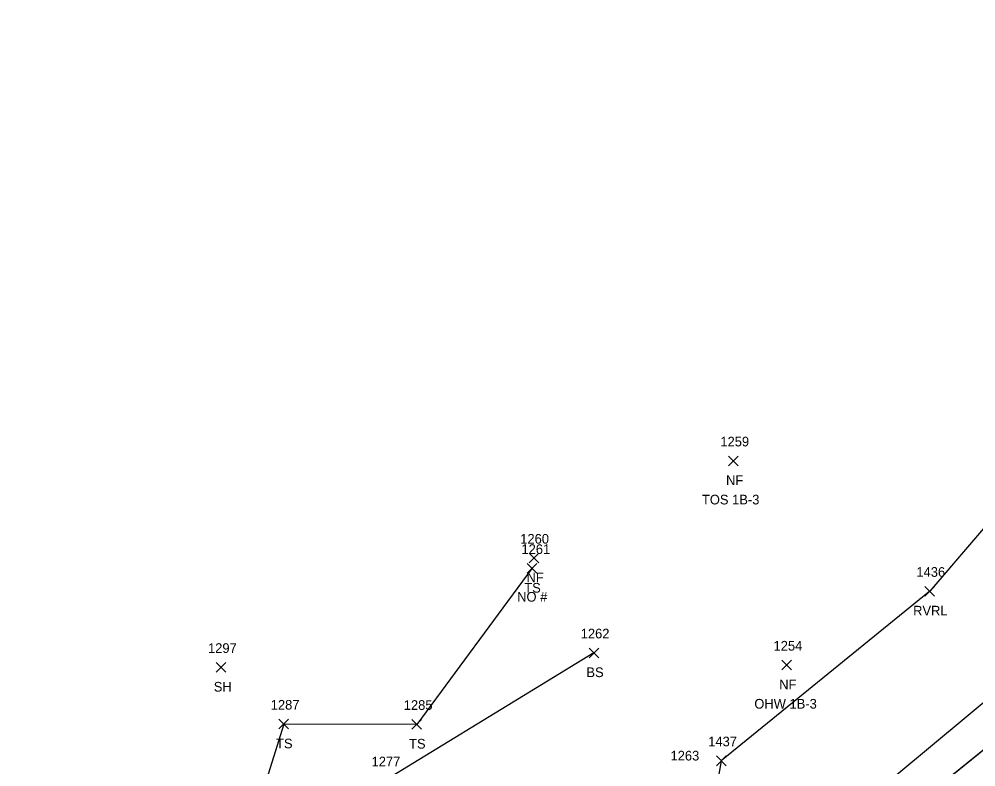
# Model space of a CAD drawing. Extents: x 1528286 to 1556263, y 492387 to 508952.
# Drawn here: x 1528818.8 to 1529016.8, y 493068.5 to 493223.1 of the extents above; entities that cross this region are included whole.
import ezdxf

# ---------------------------------------------------------------- set-up
doc = ezdxf.new("R2010")
doc.units = 0
for name, color, linetype in [('L_A', 7, 'Continuous'), ('L_C', 7, 'Continuous'), ('L_I', 7, 'Continuous'), ('L_TIC', 7, 'Continuous'), ('LAWA', 7, 'Continuous'), ('LAWE', 7, 'Continuous'), ('LELB', 7, 'Continuous')]:
    doc.layers.add(name, color=color, linetype=linetype)

msp = doc.modelspace()

# ---------------------------------------------------------------- linework, layer by layer
at = {"layer": 'L_TIC'}
for points in [[(1528965.59, 493130.75), (1528967.59, 493132.75)], [(1528967.59, 493130.75), (1528965.59, 493132.75)], [(1528965.59, 493130.75), (1528967.59, 493132.75)], [(1528967.59, 493130.75), (1528965.59, 493132.75)], [(1528924.31, 493110.64), (1528926.31, 493112.64)], [(1528926.31, 493110.64), (1528924.31, 493112.64)], [(1528924.31, 493110.64), (1528926.31, 493112.64)], [(1528926.31, 493110.64), (1528924.31, 493112.64)], [(1528923.91, 493108.51), (1528925.91, 493110.51)], [(1528925.91, 493108.51), (1528923.91, 493110.51)], [(1528923.91, 493108.51), (1528925.91, 493110.51)], [(1528925.91, 493108.51), (1528923.91, 493110.51)], [(1529006.2, 493103.78), (1529008.2, 493105.78)], [(1529008.2, 493103.78), (1529006.2, 493105.78)], [(1529006.2, 493103.78), (1529008.2, 493105.78)], [(1529008.2, 493103.78), (1529006.2, 493105.78)], [(1528936.74, 493091.04), (1528938.74, 493093.04)], [(1528938.74, 493091.04), (1528936.74, 493093.04)], [(1528936.74, 493091.04), (1528938.74, 493093.04)], [(1528938.74, 493091.04), (1528936.74, 493093.04)], [(1528859.59, 493088.04), (1528861.59, 493090.04)], [(1528861.59, 493088.04), (1528859.59, 493090.04)], [(1528859.59, 493088.04), (1528861.59, 493090.04)], [(1528861.59, 493088.04), (1528859.59, 493090.04)], [(1528976.59, 493088.52), (1528978.59, 493090.52)], [(1528978.59, 493088.52), (1528976.59, 493090.52)], [(1528976.59, 493088.52), (1528978.59, 493090.52)], [(1528978.59, 493088.52), (1528976.59, 493090.52)], [(1528872.56, 493076.31), (1528874.56, 493078.31)], [(1528874.56, 493076.31), (1528872.56, 493078.31)], [(1528872.56, 493076.31), (1528874.56, 493078.31)], [(1528874.56, 493076.31), (1528872.56, 493078.31)], [(1528900.08, 493076.26), (1528902.08, 493078.26)], [(1528902.08, 493076.26), (1528900.08, 493078.26)], [(1528900.08, 493076.26), (1528902.08, 493078.26)], [(1528902.08, 493076.26), (1528900.08, 493078.26)], [(1528963.07, 493068.72), (1528965.07, 493070.72)], [(1528965.07, 493068.72), (1528963.07, 493070.72)], [(1528963.08, 493068.72), (1528965.08, 493070.72)], [(1528965.08, 493068.72), (1528963.08, 493070.72)]]:
    msp.add_lwpolyline(points, dxfattribs=at)
at = {"layer": 'LAWA'}
for points in [[(1529161.79, 493169.98), (1529145.79, 493161.64), (1529103.54, 493137.09), (1529078.89, 493120.12), (1529036.96, 493087.03), (1528996.19, 493054.04), (1528954.46, 493025.37)], [(1529161.79, 493169.98), (1529145.79, 493161.64), (1529103.54, 493137.09), (1529078.89, 493120.12), (1529036.96, 493087.03), (1528996.19, 493054.03), (1528954.46, 493025.38)]]:
    msp.add_lwpolyline(points, dxfattribs=at)
at = {"layer": 'LAWE'}
for points in [[(1529128.54, 493223.12), (1529074.28, 493178.66), (1529038.83, 493141.68), (1529007.2, 493104.78), (1528964.07, 493069.72)], [(1529128.54, 493223.12), (1529074.28, 493178.65), (1529038.83, 493141.68), (1529007.2, 493104.78), (1528964.08, 493069.72)], [(1528993.43, 493061.12), (1529028.67, 493090.37), (1529051.82, 493126.54), (1529095.12, 493164.29)], [(1528993.43, 493061.13), (1529028.67, 493090.37), (1529051.83, 493126.54), (1529095.12, 493164.29)], [(1528964.08, 493069.72), (1528962.99, 493063.34)], [(1528964.07, 493069.72), (1528962.99, 493063.34)]]:
    msp.add_lwpolyline(points, dxfattribs=at)
at = {"layer": 'LELB'}
for points in [[(1528924.91, 493109.51), (1528901.08, 493077.26), (1528873.56, 493077.31), (1528867.18, 493056.86), (1528859.83, 493040.2), (1528841.46, 493033.43), (1528818.81, 493027.45)], [(1528924.91, 493109.51), (1528901.08, 493077.26), (1528873.56, 493077.31), (1528867.18, 493056.86), (1528859.83, 493040.2), (1528841.46, 493033.43), (1528818.81, 493027.45)], [(1528937.74, 493092.04), (1528894.42, 493065.57), (1528880.55, 493050.68), (1528899.21, 493042.4)], [(1528937.74, 493092.04), (1528894.42, 493065.57), (1528880.55, 493050.68), (1528899.21, 493042.4)]]:
    msp.add_lwpolyline(points, dxfattribs=at)

# ---------------------------------------------------------------- texts
at = {"layer": 'L_A'}
for s, p in [('NF', (1528965.07, 493126.75)), ('NF', (1528965.07, 493126.75)), ('NF', (1528923.79, 493106.64)), ('NF', (1528923.79, 493106.64)), ('TS', (1528923.32, 493104.51)), ('TS', (1528923.32, 493104.51)), ('RVRL', (1529003.77, 493099.78)), ('RVRL', (1529003.77, 493099.78)), ('BS', (1528936.18, 493087.04)), ('BS', (1528936.18, 493087.04)), ('SH', (1528859.08, 493084.04)), ('SH', (1528859.08, 493084.04)), ('NF', (1528976.07, 493084.52)), ('NF', (1528976.07, 493084.52)), ('TS', (1528871.97, 493072.31)), ('TS', (1528871.97, 493072.31)), ('TS', (1528899.49, 493072.26)), ('TS', (1528899.49, 493072.26))]:
    msp.add_text(s, height=2, dxfattribs=at).set_placement(p)
at = {"layer": 'L_C'}
for s, p in [('TOS 1B-3', (1528960.08, 493122.75)), ('TOS 1B-3', (1528960.08, 493122.75)), ('NO #', (1528921.85, 493102.64)), ('NO #', (1528921.85, 493102.64)), ('OHW 1B-3', (1528970.92, 493080.52)), ('OHW 1B-3', (1528970.92, 493080.52))]:
    msp.add_text(s, height=2, dxfattribs=at).set_placement(p)
at = {"layer": 'L_I'}
for s, p in [('1259', (1528963.89, 493134.75)), ('1259', (1528963.89, 493134.75)), ('1260', (1528922.49, 493114.64)), ('1260', (1528922.49, 493114.64)), ('1261', (1528922.74, 493112.51)), ('1261', (1528922.74, 493112.51)), ('1436', (1529004.45, 493107.78)), ('1436', (1529004.45, 493107.78)), ('1262', (1528935, 493095.04)), ('1262', (1528935, 493095.04)), ('1297', (1528857.89, 493092.04)), ('1297', (1528857.89, 493092.04)), ('1254', (1528974.9, 493092.52)), ('1254', (1528974.9, 493092.52)), ('1287', (1528870.87, 493080.31)), ('1287', (1528870.87, 493080.31)), ('1285', (1528898.39, 493080.26)), ('1285', (1528898.39, 493080.26)), ('1437', (1528961.38, 493072.72)), ('1437', (1528961.38, 493072.72)), ('1263', (1528953.58, 493069.79)), ('1263', (1528953.58, 493069.79)), ('1277', (1528891.73, 493068.57)), ('1277', (1528891.73, 493068.57))]:
    msp.add_text(s, height=2, dxfattribs=at).set_placement(p)

doc.saveas('drawing.dxf')
